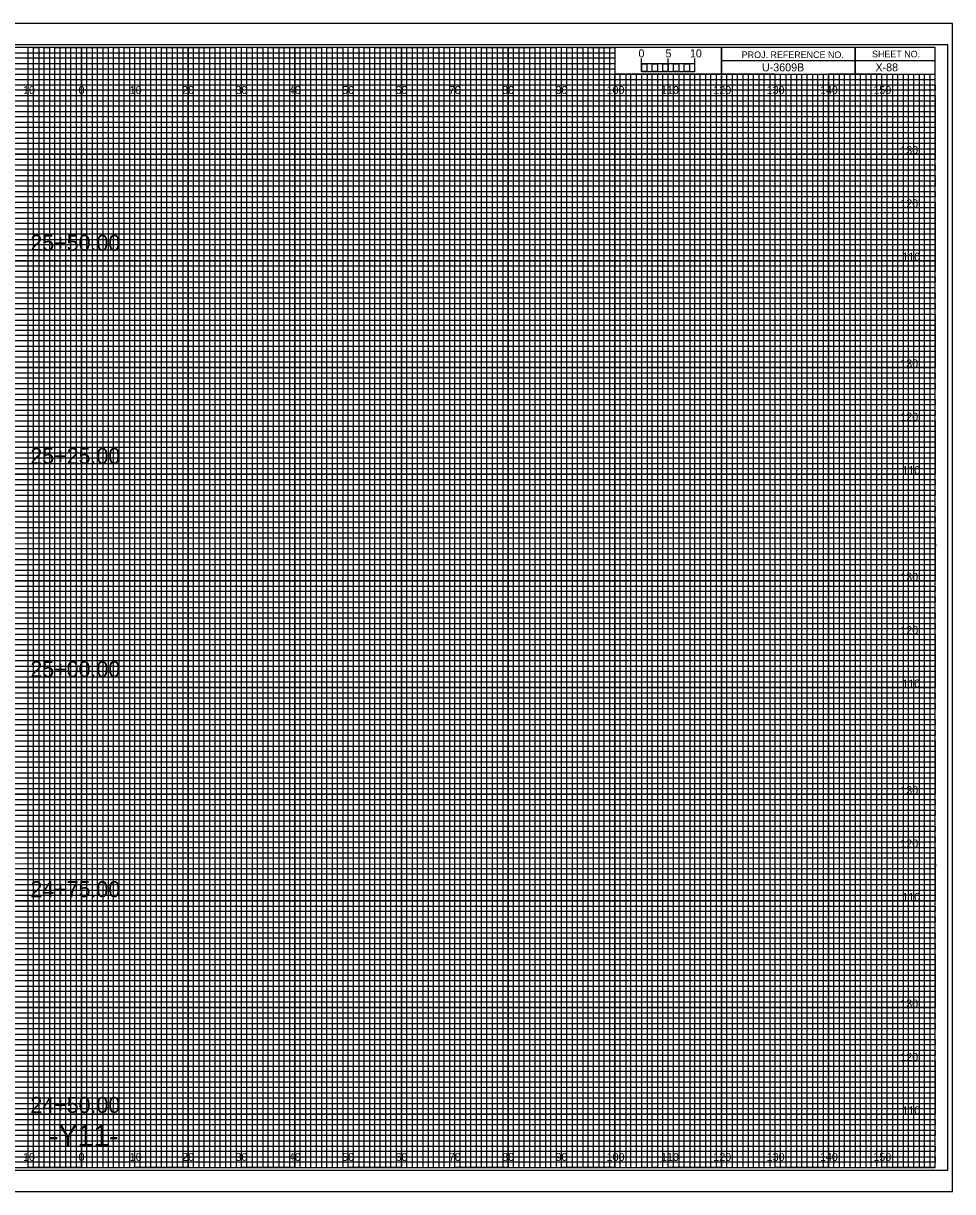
# Model space of a CAD drawing. Extents: x -13 to 323, y -5 to 3294.
# Drawn here: x 149.1 to 323.3, y 2415.5 to 2634.5 of the extents above; entities that cross this region are included whole.
import ezdxf

# ---------------------------------------------------------------- set-up
doc = ezdxf.new("R2010")
doc.units = 0
for name, color, linetype in [('Prop XS Alignment Label', 7, 'Continuous'), ('Prop XS Bar Scale Labels', 7, 'Continuous'), ('Prop XS Elevation Labels', 7, 'Continuous'), ('Prop XS Offset Labels', 7, 'Continuous'), ('Prop XS Project Number', 7, 'Continuous'), ('Prop XS Sheet Number', 7, 'Continuous'), ('Prop XS Station Labels', 7, 'Continuous'), ('Sheet Cross Section CELL', 7, 'Continuous'), ('Sheet Cross Section Grid Major CELL', 7, 'Continuous'), ('Sheet Cross Section Grid Middle CELL', 7, 'Continuous'), ('Sheet Cross Section Grid Minor 1 CELL', 7, 'Continuous'), ('Sheet Cross Section Grid Minor 2 CELL', 7, 'Continuous'), ('Sheet Cross Section Scale CELL', 7, 'Continuous'), ('Sheet Cutting Line CELL', 7, 'Continuous'), ('Sheet DOT Grid CELL', 7, 'Continuous'), ('Sheet Plot Border Inside CELL', 7, 'Continuous'), ('Sheet Plot Border Outside CELL', 7, 'Continuous')]:
    doc.layers.add(name, color=color, linetype=linetype)

msp = doc.modelspace()

# ---------------------------------------------------------------- linework, layer by layer
at = {"layer": 'Sheet Cross Section CELL'}
for p, q in [((305, 2630), (305, 2625)), ((305, 2625), (305, 2630)), ((280, 2627.5), (280, 2625)), ((320, 2627.49), (280, 2627.49)), ((280, 2625), (320, 2625))]:
    msp.add_line(p, q, dxfattribs=at)
for points in [[(320, 2630), (0, 2630), (0, 2420), (320, 2420)], [(280, 2630), (260, 2630), (260, 2625.03), (280, 2625.03)], [(320, 2630), (280, 2630), (280, 2625), (320, 2625)]]:
    msp.add_lwpolyline(points, close=True, dxfattribs=at)
at = {"layer": 'Sheet Cross Section Grid Major CELL'}
for p, q in [((150, 2630), (140, 2630)), ((150, 2420), (150, 2630)), ((170, 2630), (160, 2630)), ((160, 2630), (160, 2420)), ((170, 2420), (170, 2630)), ((190, 2630), (180, 2630)), ((180, 2630), (180, 2420)), ((190, 2420), (190, 2630)), ((210, 2630), (200, 2630)), ((200, 2630), (200, 2420)), ((210, 2420), (210, 2630)), ((230, 2630), (220, 2630)), ((220, 2630), (220, 2420)), ((230, 2420), (230, 2630)), ((250, 2630), (240, 2630)), ((240, 2630), (240, 2420)), ((250, 2420), (250, 2630)), ((260, 2630), (260, 2420)), ((270, 2420), (270, 2625)), ((290, 2625), (280, 2625)), ((280, 2625), (280, 2420)), ((290, 2420), (290, 2625)), ((310, 2625), (300, 2625)), ((300, 2625), (300, 2420)), ((310, 2420), (310, 2625)), ((160, 2420), (150, 2420)), ((180, 2420), (170, 2420)), ((200, 2420), (190, 2420)), ((220, 2420), (210, 2420)), ((240, 2420), (230, 2420)), ((260, 2420), (250, 2420)), ((280, 2420), (270, 2420)), ((300, 2420), (290, 2420)), ((320, 2420), (310, 2420)), ((320, 2420), (320, 2420))]:
    msp.add_line(p, q, dxfattribs=at)
for points in [[(0, 2620), (320, 2620), (320, 2610), (0, 2610)], [(0, 2600), (320, 2600), (320, 2590), (0, 2590)], [(0, 2580), (320, 2580), (320, 2570), (0, 2570)], [(0, 2560), (320, 2560), (320, 2550), (0, 2550)], [(0, 2540), (320, 2540), (320, 2530), (0, 2530)], [(0, 2520), (320, 2520), (320, 2510), (0, 2510)], [(0, 2500), (320, 2500), (320, 2490), (0, 2490)], [(0, 2480), (320, 2480), (320, 2470), (0, 2470)], [(0, 2460), (320, 2460), (320, 2450), (0, 2450)], [(0, 2440), (320, 2440), (320, 2430), (0, 2430)]]:
    msp.add_lwpolyline(points, dxfattribs=at)
at = {"layer": 'Sheet Cross Section Grid Middle CELL'}
for points in [[(145, 2420), (155, 2420), (155, 2630), (165, 2630), (165, 2420), (175, 2420), (175, 2630), (185, 2630), (185, 2420), (195, 2420), (195, 2630), (205, 2630), (205, 2420), (215, 2420), (215, 2630), (225, 2630), (225, 2420), (235, 2420), (235, 2630), (245, 2630), (245, 2420), (255, 2420), (255, 2630), (259.93, 2630), (260, 2630), (260, 2625), (264.99, 2625), (264.99, 2420), (275, 2420), (275, 2625), (285, 2625), (285, 2420), (295, 2420), (295, 2625), (305, 2625), (305, 2420), (315, 2420), (315, 2625)], [(0, 2625), (275, 2625)], [(0, 2605), (320, 2605), (320, 2615), (0, 2615)], [(0, 2585), (320, 2585), (320, 2595), (0, 2595)], [(0, 2565), (320, 2565), (320, 2575), (0, 2575)], [(0, 2545), (320, 2545), (320, 2555), (0, 2555)], [(0, 2525), (320, 2525), (320, 2535), (0, 2535)], [(0, 2505), (320, 2505), (320, 2515), (0, 2515)], [(0, 2485), (320, 2485), (320, 2495), (0, 2495)], [(0, 2465), (320, 2465), (320, 2475), (0, 2475)], [(0, 2445), (320, 2445), (320, 2455), (0, 2455)], [(0, 2425), (320, 2425), (320, 2435), (0, 2435)]]:
    msp.add_lwpolyline(points, dxfattribs=at)
at = {"layer": 'Sheet Cross Section Grid Minor 1 CELL'}
for p, q in [((0, 2629), (260, 2629)), ((260, 2629), (260, 2627.98)), ((260, 2627.98), (0, 2627.98)), ((0, 2627), (260, 2627)), ((260, 2625.89), (0, 2625.89)), ((260, 2627), (260, 2625.89)), ((0, 2624), (320, 2624))]:
    msp.add_line(p, q, dxfattribs=at)
for points in [[(0, 2623), (270, 2623), (320, 2623), (320, 2622), (0, 2622)], [(0, 2621), (320, 2621), (320, 2619), (0, 2619)], [(0, 2618), (320, 2618), (320, 2617), (0, 2616.98)], [(0, 2616), (320, 2616), (320, 2614), (0, 2614)], [(0, 2613), (320, 2613), (320, 2612), (0, 2612)], [(0, 2611), (320, 2611), (320, 2609), (0, 2609)], [(0, 2608), (320, 2608), (320, 2607), (0, 2607)], [(0, 2606), (320, 2606), (320, 2604), (0, 2604)], [(0, 2603), (320, 2603), (320, 2602), (0, 2602)], [(0, 2601), (320, 2601), (320, 2599), (0, 2599)], [(0, 2598), (320, 2598), (320, 2597), (0, 2597)], [(0, 2596), (320, 2596), (320, 2593.95), (320, 2593), (320, 2592), (0, 2592)], [(0, 2594), (320, 2594), (320, 2593), (0, 2593)], [(0, 2591), (320, 2591), (320, 2589), (0, 2589.03)], [(0, 2589.03), (320, 2589), (320, 2588), (0, 2588)], [(0, 2587), (320, 2587), (320, 2586), (0, 2586)], [(0, 2584), (320, 2584), (320, 2583), (0, 2583)], [(0, 2582), (320, 2582), (320, 2581), (0, 2581)], [(-0.07, 2578.89), (320, 2578.89), (320, 2577.88), (-0.07, 2577.88)], [(0, 2577), (320, 2577), (320, 2576), (0, 2576)], [(0, 2574), (320, 2574), (320, 2573), (0, 2573)], [(0, 2572), (320, 2572), (320, 2571), (0, 2571)], [(0, 2569), (320, 2569), (320, 2568), (0, 2568)], [(0, 2567), (320, 2567), (320, 2566), (0, 2566)], [(0, 2564), (320, 2564), (320, 2563), (0, 2563)], [(0, 2562), (320, 2562), (320, 2561), (0, 2561)], [(0, 2559), (320, 2559), (319.99, 2557.98), (0, 2558)], [(0, 2557), (320, 2557), (320, 2556), (0, 2556)], [(0, 2554), (320, 2554), (320, 2553), (0, 2553)], [(0, 2552), (320, 2552), (320, 2551), (0, 2551)], [(0, 2549), (320, 2549), (320, 2548), (0, 2548)], [(0, 2547), (320, 2547), (320, 2546), (0, 2546)], [(0, 2544), (320, 2544), (320, 2543), (0, 2543)], [(0, 2542), (320, 2542), (320, 2541), (0, 2541)], [(0, 2539), (320, 2539), (320, 2538), (0, 2538)], [(0, 2536.99), (320.07, 2536.91), (320, 2536), (0, 2536)], [(0, 2534), (320, 2534), (320, 2533), (0, 2533)], [(0, 2532), (320, 2532), (320, 2531), (0, 2531)], [(0, 2529), (320, 2529), (320, 2528), (0, 2528)], [(0, 2527), (320, 2527), (320, 2526), (0, 2526)], [(0, 2524), (320, 2524), (320, 2523), (0, 2523)], [(0, 2522), (320, 2522), (320, 2521), (0, 2521)], [(0, 2519), (320, 2519), (320, 2518), (0, 2518)], [(0, 2517), (320, 2517), (320, 2516), (0, 2516)], [(0, 2514), (320, 2514), (320, 2513), (0, 2513)], [(0, 2512), (320, 2512), (320, 2511), (0, 2511)], [(0, 2509), (320, 2509), (320, 2508), (0, 2508)], [(0, 2507), (320, 2507), (320, 2506), (0, 2506)], [(0, 2504), (320, 2504), (320, 2503), (0, 2503)], [(0, 2502), (320, 2502), (320, 2501), (0, 2501)], [(0, 2499), (320, 2499), (319.99, 2497.98), (0, 2498)], [(0, 2497), (320, 2497), (320, 2496), (0, 2496)], [(0, 2494), (320, 2494), (320, 2493), (0, 2493)], [(0, 2492), (320, 2492), (320, 2491), (0, 2491)], [(0, 2489), (320, 2489), (320, 2488), (0, 2488)], [(0, 2487), (320, 2487), (320, 2486), (0, 2486)], [(0, 2484), (320, 2484), (320, 2483), (0, 2483)], [(0, 2482), (320, 2482), (320, 2481), (0, 2481)], [(0, 2479), (320, 2479), (320, 2478), (0, 2478)], [(0, 2476.99), (320.07, 2476.91), (320, 2476), (0, 2476)], [(0, 2474), (320, 2474), (320, 2473), (0, 2473)], [(0, 2472), (320, 2472), (320, 2471), (0, 2471)], [(0, 2469), (320, 2469), (320, 2468), (0, 2468)], [(0, 2467), (320, 2467), (320, 2466), (0, 2466)], [(0, 2464), (320, 2464), (320, 2463), (0, 2463)], [(0, 2462), (320, 2462), (320, 2461), (0, 2461)], [(0, 2459), (320, 2459), (320, 2458), (0, 2458)], [(0, 2457), (320, 2457), (320, 2456), (0, 2456)], [(0, 2454), (320, 2454), (320, 2453), (0, 2453)], [(0, 2452), (320, 2452), (320, 2451), (0, 2451)], [(0, 2449), (320, 2449), (320, 2448), (0, 2448)], [(0, 2447), (320, 2447), (320, 2446), (0, 2446)], [(0, 2444), (320, 2444), (320, 2443), (0, 2443)], [(0, 2442), (320, 2442), (320, 2441), (0, 2441)], [(0, 2439), (320, 2439), (320, 2438), (0, 2438)], [(0, 2437), (320, 2437), (320, 2436), (0, 2436)], [(0, 2434), (320, 2434), (320, 2433), (0, 2433)], [(0, 2432), (320, 2432), (320, 2431), (0, 2431)], [(0, 2429), (320, 2429), (320, 2428), (0, 2428)], [(0, 2427), (320, 2427), (320, 2426), (0, 2426)], [(0, 2424), (320, 2424), (320, 2423), (0, 2423)], [(0, 2422), (320, 2422), (320, 2421), (0, 2421)]]:
    msp.add_lwpolyline(points, dxfattribs=at)
at = {"layer": 'Sheet Cross Section Grid Minor 2 CELL'}
for p, q in [((267, 2625), (266.01, 2625)), ((266.01, 2625), (266.01, 2420)), ((267, 2420), (267, 2625)), ((269, 2625), (268, 2625)), ((268, 2625), (268, 2420)), ((269, 2420), (269, 2625)), ((266.01, 2420), (265, 2420)), ((268, 2420), (267, 2420))]:
    msp.add_line(p, q, dxfattribs=at)
for points in [[(150, 2420), (151, 2420), (151, 2630), (152, 2630), (152, 2420)], [(152, 2420), (153, 2420), (153, 2630), (154, 2630), (154, 2420)], [(155, 2420), (156, 2420), (156, 2630), (157, 2630), (157, 2420)], [(157, 2420), (158, 2420), (158, 2630), (159, 2630), (159, 2420)], [(160, 2420), (161, 2420), (161, 2630), (162, 2630), (162, 2420)], [(162, 2420), (163, 2420), (163, 2630), (164, 2630), (164, 2420)], [(165, 2420), (166, 2420), (166, 2630), (167, 2630), (167, 2420)], [(167, 2420), (168, 2420), (168, 2630), (169, 2630), (169, 2420)], [(170, 2420), (171, 2420), (171, 2630), (172, 2630), (172, 2420)], [(172, 2420), (173, 2420), (173, 2630), (174, 2630), (174, 2420)], [(175, 2420), (176, 2420), (176, 2630), (177, 2630), (177, 2420)], [(177, 2420), (178, 2420), (178, 2630), (179, 2630), (179, 2420)], [(180, 2420), (181, 2420), (181, 2630), (182, 2630), (182, 2420)], [(182, 2420), (183, 2420), (183, 2630), (184, 2630), (184, 2420)], [(185, 2420), (186, 2420), (186, 2630), (187, 2630), (187, 2420)], [(187, 2420), (188, 2420), (188, 2630), (189, 2630), (189, 2420)], [(190, 2420), (191, 2420), (191, 2630), (192, 2630), (192, 2420)], [(192, 2420), (193, 2420), (193, 2630), (194, 2630), (194, 2420)], [(195, 2420), (196, 2420), (196, 2630), (197, 2630), (197, 2420)], [(197, 2420), (198, 2420), (198, 2630), (199, 2630), (199, 2420)], [(200, 2420), (201, 2420), (201, 2630), (202, 2630), (202, 2420)], [(202, 2420), (203, 2420), (203, 2630), (204, 2630), (204, 2420)], [(205, 2420), (206, 2420), (206, 2630), (207, 2630), (207, 2420)], [(207, 2420), (208, 2420), (208, 2630), (209, 2630), (209, 2420)], [(210, 2420), (211, 2420), (211, 2630), (212, 2630), (212, 2420)], [(212, 2420), (213, 2420), (213, 2630), (214, 2630), (214, 2420)], [(215, 2420), (216, 2420), (216, 2630), (217, 2630), (217, 2420)], [(217, 2420), (218, 2420), (218, 2630), (219, 2630), (219, 2420)], [(220, 2420), (221, 2420), (221, 2630), (222, 2630), (222, 2420)], [(222, 2420), (223, 2420), (223, 2630), (224, 2630), (224, 2420)], [(225, 2420), (226, 2420), (226, 2630), (227, 2630), (227, 2420)], [(227, 2420), (228, 2420), (228, 2630), (229, 2630), (229, 2420)], [(230, 2420), (231, 2420), (231, 2630), (232, 2630), (232, 2420)], [(232, 2420), (233, 2420), (233, 2630), (234, 2630), (234, 2420)], [(235, 2420), (236, 2420), (236, 2630), (237, 2630), (237, 2420)], [(237, 2420), (238, 2420), (238, 2630), (239, 2630), (239, 2420)], [(240, 2420), (241, 2420), (241, 2630), (242, 2630), (242, 2420)], [(242, 2420), (243, 2420), (243, 2630), (244, 2630), (244, 2420)], [(245, 2420), (246, 2420), (246, 2630), (247, 2630), (247, 2420)], [(247, 2420), (248, 2420), (248, 2630), (249, 2630), (249, 2420)], [(250, 2420), (251, 2420), (251, 2630), (252, 2630), (252, 2420)], [(252, 2420), (253, 2420), (253, 2630), (254, 2630), (254, 2420)], [(255, 2420), (256, 2420), (256, 2630), (257, 2630), (257, 2420)], [(257, 2420), (258, 2420), (258, 2630), (259, 2630), (259, 2420)], [(260, 2420), (261, 2420), (261, 2625), (262.02, 2625), (262.02, 2420)], [(262, 2420), (263, 2420), (263, 2625), (263.99, 2625), (263.99, 2420)], [(270, 2420), (270.98, 2420), (270.98, 2625), (272, 2625), (272, 2420)], [(272, 2420), (273, 2420), (273, 2625), (274.05, 2625), (274.05, 2420)], [(275, 2420), (276, 2420), (276, 2625), (277, 2625), (277, 2420)], [(277, 2420), (278, 2420), (278, 2625), (279, 2625), (279, 2420)], [(280, 2420), (281, 2420), (281, 2625), (282, 2625), (282, 2420)], [(282, 2420), (283, 2420), (283, 2625), (284, 2625), (284, 2420)], [(285, 2420), (286, 2420), (286, 2625), (287, 2625), (287, 2420)], [(287, 2420), (288, 2420), (288, 2625), (289, 2625), (289, 2420)], [(290, 2420), (291, 2420), (291, 2625), (292, 2625), (292, 2420)], [(292, 2420), (293, 2420), (293, 2625), (294, 2625), (294, 2420)], [(295, 2420), (296, 2420), (296, 2625), (297, 2625), (297, 2420)], [(297, 2420), (298, 2420), (298, 2625), (299, 2625), (299, 2420)], [(300, 2420), (301, 2420), (301, 2625), (302, 2625), (302, 2420)], [(302, 2420), (303, 2420), (303, 2625), (304, 2625), (304, 2420)], [(305, 2420), (306, 2420), (306, 2625), (307, 2625), (307, 2420)], [(307, 2420), (308, 2420), (308, 2625), (309, 2625), (309, 2420)], [(310, 2420), (311, 2420), (311, 2625), (312, 2625), (312, 2420)], [(312, 2420), (313, 2420), (313, 2625), (314, 2625), (314, 2420)], [(315, 2420), (316, 2420), (316, 2625), (317, 2625), (317, 2420)], [(317, 2420), (318, 2420), (318, 2625), (319, 2625), (319, 2420)]]:
    msp.add_lwpolyline(points, dxfattribs=at)
at = {"layer": 'Sheet Cross Section Scale CELL'}
for p, q in [((265, 2625.49), (265, 2627.9)), ((265, 2626.9), (265, 2627.9)), ((270, 2625.49), (270, 2627.9)), ((275, 2625.49), (275, 2627.9)), ((275, 2626.9), (275, 2627.9))]:
    msp.add_line(p, q, dxfattribs=at)
for points in [[(275, 2626.9), (265, 2626.9), (265, 2625.49), (275, 2625.49)], [(265, 2626.9), (266, 2626.9), (266, 2625.49), (265, 2625.49)], [(267, 2626.9), (268, 2626.9), (268, 2625.49), (267, 2625.49)], [(269, 2626.9), (270, 2626.9), (270, 2625.49), (269, 2625.49)], [(271, 2626.9), (272, 2626.9), (272, 2625.49), (271, 2625.49)], [(273, 2626.9), (274, 2626.9), (274, 2625.49), (273, 2625.49)]]:
    msp.add_lwpolyline(points, close=True, dxfattribs=at)
at = {"layer": 'Sheet Cutting Line CELL'}
for p, q in [((323.3, 2634.5), (-13.4, 2634.5)), ((-13.4, 2415.5), (323.3, 2415.5))]:
    msp.add_line(p, q, dxfattribs=at)
at = {"layer": 'Sheet DOT Grid CELL'}
for p, q in [((150, 2420), (150, 2630)), ((160, 2420), (160, 2630)), ((170, 2420), (170, 2630)), ((180, 2420), (180, 2630)), ((190, 2420), (190, 2630)), ((200, 2420), (200, 2630)), ((210, 2420), (210, 2630)), ((220, 2420), (220, 2630)), ((230, 2420), (230, 2630)), ((240, 2420), (240, 2630)), ((250, 2420), (250, 2630)), ((260, 2420), (260, 2624.69)), ((270, 2420), (270, 2624.69)), ((280, 2420), (280, 2624.69)), ((290, 2420), (290, 2624.69)), ((300, 2420), (300, 2624.69)), ((310, 2420), (310, 2624.69)), ((0, 2620), (320, 2620)), ((0, 2610), (320, 2610)), ((0, 2600), (320, 2600)), ((0, 2590), (320, 2590)), ((0, 2580), (320, 2580)), ((0, 2570), (320, 2570)), ((0, 2560), (320, 2560)), ((0, 2550), (320, 2550)), ((0, 2540), (320, 2540)), ((0, 2530), (320, 2530)), ((0, 2520), (320, 2520)), ((0, 2510), (320, 2510)), ((0, 2500), (320, 2500)), ((0, 2490), (320, 2490)), ((0, 2480), (320, 2480)), ((0, 2470), (320, 2470)), ((0, 2460), (320, 2460)), ((0, 2450), (320, 2450)), ((0, 2440), (320, 2440)), ((0, 2430), (320, 2430))]:
    msp.add_line(p, q, dxfattribs=at)
at = {"layer": 'Sheet Plot Border Inside CELL'}
msp.add_lwpolyline([(-10.8, 2419.5), (322.4, 2419.5), (322.4, 2630.5), (-10.8, 2630.5)], close=True, dxfattribs=at)
at = {"layer": 'Sheet Plot Border Outside CELL'}
msp.add_lwpolyline([(-13.4, 2415.5), (323.3, 2415.5), (323.3, 2634.5), (-13.4, 2634.5)], close=True, dxfattribs=at)

# ---------------------------------------------------------------- texts
at = {"layer": 'Prop XS Alignment Label'}
msp.add_text('-Y11-', height=4, dxfattribs=at).set_placement((153.89, 2424))
at = {"layer": 'Prop XS Bar Scale Labels'}
for s, p in [('5', (269.47, 2628.12)), ('10', (274.04, 2628.12))]:
    msp.add_text(s, height=1.5, dxfattribs=at).set_placement(p)
at = {"layer": 'Prop XS Elevation Labels'}
for s, p in [('130', (313.49, 2610)), ('120', (313.5, 2600)), ('110', (313.88, 2590)), ('130', (313.49, 2570)), ('120', (313.5, 2560)), ('110', (313.88, 2550)), ('130', (313.49, 2530)), ('120', (313.5, 2520)), ('110', (313.88, 2510)), ('130', (313.49, 2490)), ('120', (313.5, 2480)), ('110', (313.88, 2470)), ('130', (313.49, 2450)), ('120', (313.5, 2440)), ('110', (313.88, 2430))]:
    msp.add_text(s, height=1.5, dxfattribs=at).set_placement(p)
at = {"layer": 'Prop XS Offset Labels'}
for s, p in [('10', (149.04, 2621.25)), ('0', (159.45, 2621.25)), ('0', (159.45, 2621.25)), ('10', (169.04, 2621.25)), ('20', (178.86, 2621.25)), ('30', (188.86, 2621.25)), ('40', (198.86, 2621.25)), ('50', (208.86, 2621.25)), ('60', (218.86, 2621.25)), ('70', (228.86, 2621.25)), ('80', (238.86, 2621.25)), ('90', (248.86, 2621.25)), ('100', (258.44, 2621.25)), ('110', (268.62, 2621.25)), ('120', (278.44, 2621.25)), ('130', (288.44, 2621.25)), ('140', (298.44, 2621.25)), ('150', (308.44, 2621.25)), ('10', (149.04, 2421.25)), ('0', (159.45, 2421.25)), ('0', (159.45, 2421.25)), ('10', (169.04, 2421.25)), ('20', (178.86, 2421.25)), ('30', (188.86, 2421.25)), ('40', (198.86, 2421.25)), ('50', (208.86, 2421.25)), ('60', (218.86, 2421.25)), ('70', (228.86, 2421.25)), ('80', (238.86, 2421.25)), ('90', (248.86, 2421.25)), ('100', (258.44, 2421.25)), ('110', (268.62, 2421.25)), ('120', (278.44, 2421.25)), ('130', (288.44, 2421.25)), ('140', (298.44, 2421.25)), ('150', (308.44, 2421.25))]:
    msp.add_text(s, height=1.5, dxfattribs=at).set_placement(p)
at = {"layer": 'Prop XS Project Number'}
msp.add_text('U-3609B', height=1.5, dxfattribs=at).set_placement((287.56, 2625.5))
at = {"layer": 'Prop XS Sheet Number'}
msp.add_text('X-88', height=1.5, dxfattribs=at).set_placement((308.83, 2625.5))
at = {"layer": 'Prop XS Station Labels'}
for s, p in [('25+50.00', (150.41, 2591.87)), ('25+25.00', (150.41, 2551.91)), ('25+00.00', (150.41, 2511.95)), ('24+75.00', (150.41, 2470.7)), ('24+50.00', (150.41, 2430.25))]:
    msp.add_text(s, height=3, dxfattribs=at).set_placement(p)
at = {"layer": 'Sheet Cross Section CELL'}
for s, p in [('PROJ. REFERENCE NO.', (283.77, 2627.99)), ('SHEET NO.', (308.19, 2628.12))]:
    msp.add_text(s, height=1.25, dxfattribs=at).set_placement(p)
at = {"layer": 'Sheet Cross Section Scale CELL'}
msp.add_text('0', height=1.5, dxfattribs=at).set_placement((264.41, 2628.12))

doc.saveas('drawing.dxf')
